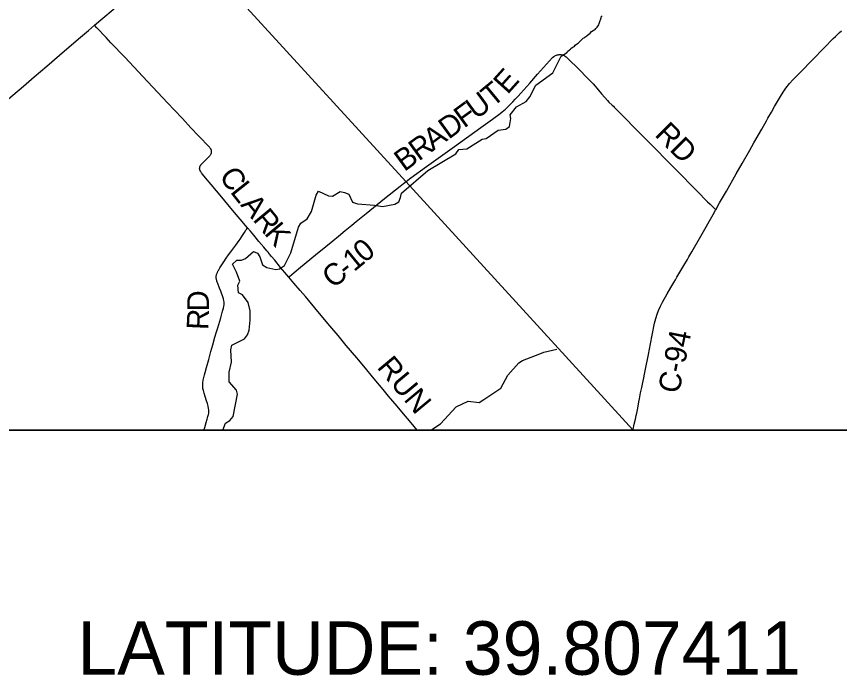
# Model space of a CAD drawing. Extents: x -1.4 to 35.4, y 0 to 22.
# Drawn here: x 19.08 to 21.235, y 12.413 to 14.137 of the extents above; entities that cross this region are included whole.
import ezdxf

# ---------------------------------------------------------------- set-up
doc = ezdxf.new("R2010")
doc.units = 0
for name, color, linetype in [('GM_X_County_Road', 7, 'Continuous'), ('GM_X_County_Road_Text', 7, 'Continuous'), ('GM_X_Minor_River', 7, 'Continuous'), ('GM_X_Township_Road', 7, 'Continuous'), ('GM_X_Township_Road_Text', 7, 'Continuous'), ('SC_Scratch1', 7, 'Continuous'), ('SH_Border', 7, 'Continuous'), ('SH_Text', 7, 'Continuous')]:
    doc.layers.add(name, color=color, linetype=linetype)

msp = doc.modelspace()

# ---------------------------------------------------------------- linework, layer by layer
at = {"layer": 'GM_X_County_Road'}
msp.add_line((20.6943, 13.0546), (20.6944, 13.0551), dxfattribs=at)
for points in [[(19.285, 14.1142), (19.3064, 14.1326), (19.3333, 14.1559), (19.3644, 14.1828), (19.38, 14.1961), (19.3968, 14.2106)], [(19.0431, 13.9076), (19.0988, 13.9553), (19.1264, 13.979), (19.1596, 14.0074), (19.193, 14.0362), (19.2247, 14.0631), (19.2479, 14.0829), (19.2693, 14.1008), (19.285, 14.1142)], [(20.9107, 13.6315), (20.9208, 13.6495), (20.9385, 13.6802), (20.9644, 13.7255), (20.98, 13.7527), (20.9996, 13.787), (21.0107, 13.8064), (21.0313, 13.8422), (21.0439, 13.8639), (21.0474, 13.8711), (21.0565, 13.8868), (21.0648, 13.9013), (21.0803, 13.9282), (21.0871, 13.9393), (21.0946, 13.95), (21.1038, 13.9616), (21.1133, 13.9722), (21.1323, 13.9918), (21.1642, 14.024), (21.1947, 14.0551), (21.2185, 14.0794), (21.2241, 14.0851), (21.2347, 14.0956), (21.2398, 14.1)], [(20.1001, 13.7052), (20.1125, 13.7148), (20.1538, 13.7446), (20.2273, 13.7972), (20.2957, 13.8464), (20.3264, 13.8682), (20.3466, 13.8837), (20.3518, 13.8881), (20.36, 13.8947), (20.3633, 13.8976), (20.3692, 13.9032), (20.38, 13.9143), (20.386, 13.9206), (20.3932, 13.9284), (20.4007, 13.9367), (20.424, 13.963), (20.4445, 13.9861), (20.4757, 14.0213), (20.4833, 14.0295), (20.4868, 14.0327), (20.4884, 14.0337), (20.4898, 14.0345), (20.4917, 14.0354), (20.4937, 14.0362), (20.4959, 14.0368), (20.4984, 14.0373), (20.5002, 14.0375), (20.5022, 14.0376), (20.5043, 14.0376), (20.5061, 14.0375), (20.5078, 14.0372), (20.5093, 14.0369), (20.5108, 14.0364), (20.5122, 14.0359), (20.5136, 14.0352), (20.5148, 14.0346), (20.517, 14.0331), (20.5188, 14.0318), (20.5206, 14.0303), (20.5334, 14.0181), (20.5435, 14.0081), (20.5835, 13.9675), (20.5896, 13.9609), (20.5948, 13.9548), (20.5992, 13.9496), (20.6121, 13.9345), (20.6203, 13.9251), (20.6274, 13.9175), (20.6312, 13.9134), (20.6397, 13.9052), (20.6428, 13.9022), (20.645, 13.9001), (20.6511, 13.894), (20.6554, 13.8895), (20.6606, 13.8842), (20.6657, 13.8789), (20.671, 13.8737), (20.6752, 13.8692), (20.6964, 13.8474), (20.7191, 13.8246), (20.7526, 13.7907), (20.7823, 13.7608), (20.8116, 13.7313), (20.8569, 13.6854), (20.8674, 13.6747), (20.8834, 13.6584), (20.8895, 13.6523), (20.8957, 13.6462), (20.9015, 13.6406), (20.9107, 13.6315)], [(19.7929, 13.4552), (19.7953, 13.4572), (19.8076, 13.4674), (19.8242, 13.4812), (19.8631, 13.5134), (19.89, 13.5354), (19.9084, 13.5503), (19.9229, 13.5621), (19.9408, 13.577), (19.958, 13.5914), (19.9696, 13.6008), (19.9961, 13.6214), (20.0433, 13.6606), (20.0843, 13.6928), (20.0934, 13.7), (20.1001, 13.7052)], [(20.6944, 13.0551), (20.6946, 13.0564), (20.6976, 13.0703), (20.7005, 13.0837), (20.7024, 13.0928), (20.7038, 13.0995), (20.7055, 13.108), (20.7075, 13.1176), (20.7097, 13.1286), (20.7112, 13.1366), (20.712, 13.1415), (20.7141, 13.1524), (20.717, 13.1664), (20.7189, 13.1755), (20.7224, 13.1919), (20.7244, 13.2016), (20.7296, 13.2278), (20.7312, 13.2357), (20.7345, 13.2528), (20.7398, 13.2802), (20.7443, 13.3034), (20.7508, 13.3345), (20.7539, 13.3465), (20.7573, 13.3579), (20.7611, 13.3678), (20.7662, 13.3792), (20.7716, 13.3897), (20.7838, 13.4114), (20.7935, 13.428), (20.8011, 13.4409), (20.8052, 13.4478), (20.8093, 13.4548), (20.8276, 13.4858), (20.8366, 13.5014), (20.8403, 13.5079), (20.848, 13.5214), (20.872, 13.5625), (20.9043, 13.6194), (20.91, 13.6304), (20.9107, 13.6315)], [(19.5708, 13.0546), (19.573, 13.0617), (19.5771, 13.0746), (19.5798, 13.0835), (19.5817, 13.0906), (19.5829, 13.0954), (19.5836, 13.0996), (19.5839, 13.1038), (19.5837, 13.108), (19.5833, 13.1116), (19.582, 13.1175), (19.5801, 13.1247), (19.5782, 13.1312), (19.5745, 13.1431), (19.5716, 13.1519), (19.5697, 13.1585), (19.5686, 13.1635), (19.568, 13.1685), (19.5679, 13.1736), (19.5683, 13.1786), (19.5694, 13.1854), (19.5701, 13.189), (19.571, 13.1927), (19.5728, 13.1995), (19.5744, 13.206), (19.578, 13.2191), (19.5838, 13.2394), (19.5866, 13.2503), (19.5895, 13.2604), (19.5946, 13.2784), (19.6, 13.2977), (19.6043, 13.3121), (19.6071, 13.3223), (19.6149, 13.3487), (19.6177, 13.3588), (19.6199, 13.366), (19.6223, 13.3743), (19.6233, 13.379), (19.6239, 13.3828), (19.6242, 13.3857), (19.6242, 13.3897), (19.6235, 13.3934), (19.6224, 13.398), (19.6209, 13.4032), (19.6169, 13.4133), (19.615, 13.4184), (19.6117, 13.4264), (19.6071, 13.4382), (19.6063, 13.4404), (19.6056, 13.4424), (19.605, 13.4444), (19.6044, 13.4463), (19.6039, 13.4485), (19.6036, 13.4502), (19.6033, 13.4518), (19.6031, 13.4535), (19.6031, 13.4551), (19.6032, 13.4568), (19.6034, 13.4583), (19.6037, 13.4599), (19.6042, 13.4617), (19.6048, 13.4635), (19.6056, 13.4655), (19.6065, 13.4676), (19.6077, 13.4704), (19.609, 13.4727), (19.6131, 13.4797), (19.6231, 13.4955), (19.6296, 13.5052), (19.6357, 13.5138), (19.6412, 13.5213), (19.6468, 13.5287), (19.6546, 13.5392), (19.6632, 13.5513), (19.6657, 13.5549), (19.6719, 13.5641), (19.6769, 13.5718), (19.6811, 13.578), (19.6821, 13.5795), (19.6853, 13.584)]]:
    msp.add_lwpolyline(points, dxfattribs=at)
at = {"layer": 'GM_X_Minor_River'}
for points in [[(20.5061, 14.0333), (20.5203, 14.0424), (20.5214, 14.0428), (20.523, 14.0458), (20.5276, 14.0499), (20.5303, 14.0517), (20.5318, 14.0536), (20.5352, 14.0562), (20.5383, 14.0581), (20.5406, 14.0592), (20.5429, 14.0622), (20.5464, 14.0652), (20.5502, 14.0678), (20.5525, 14.0689), (20.5537, 14.0712), (20.556, 14.073), (20.5579, 14.0745), (20.5613, 14.0775), (20.5636, 14.0801), (20.5659, 14.0813), (20.5682, 14.0831), (20.5705, 14.085), (20.5732, 14.0868), (20.5751, 14.0887), (20.5786, 14.0909), (20.582, 14.0932), (20.5851, 14.0977), (20.5897, 14.1007), (20.5928, 14.1025), (20.5947, 14.1036), (20.5966, 14.1059), (20.5985, 14.1078), (20.6005, 14.1096), (20.6043, 14.1153), (20.6059, 14.1187), (20.6067, 14.1213), (20.6075, 14.124), (20.6086, 14.1266), (20.6094, 14.1289), (20.6106, 14.1334), (20.6107, 14.1365), (20.613, 14.1387)], [(19.8413, 13.6078), (19.8526, 13.6272), (19.8652, 13.6701), (19.8711, 13.6799), (19.897, 13.668), (19.9075, 13.667), (19.9275, 13.6791), (19.9388, 13.6766), (19.9504, 13.6725), (19.9598, 13.6511), (19.973, 13.6467), (20.0172, 13.6439), (20.0383, 13.6396), (20.071, 13.6458), (20.081, 13.652), (20.0857, 13.6633), (20.0878, 13.6746), (20.1571, 13.7346), (20.2307, 13.7782), (20.2384, 13.7894), (20.2589, 13.7905), (20.2991, 13.8166), (20.3094, 13.8183), (20.3412, 13.8396), (20.3613, 13.8426), (20.3709, 13.8496), (20.374, 13.87), (20.373, 13.8795), (20.3894, 13.9004), (20.4142, 13.9151), (20.4239, 13.9266), (20.4401, 13.9577), (20.4846, 13.9898), (20.5061, 14.0333)], [(19.6206, 13.0546), (19.6279, 13.0727), (19.6391, 13.0797), (19.648, 13.0901), (19.6587, 13.1491), (19.6559, 13.1591), (19.6373, 13.1815), (19.6371, 13.2065), (19.6429, 13.2326), (19.6417, 13.2653), (19.6445, 13.277), (19.6775, 13.2934), (19.6853, 13.3042), (19.6897, 13.3163), (19.6922, 13.3428), (19.6919, 13.3667), (19.6866, 13.3889), (19.6722, 13.4089), (19.6613, 13.4144), (19.6598, 13.4342), (19.6646, 13.4447), (19.656, 13.4681), (19.6458, 13.4892), (19.657, 13.4996), (19.6695, 13.4993), (19.6795, 13.5037), (19.7011, 13.5222), (19.7112, 13.5182), (19.7175, 13.5086), (19.7243, 13.4875), (19.7355, 13.4805), (19.7594, 13.4754), (19.7689, 13.4768), (19.7823, 13.4852), (19.7982, 13.5187), (19.8185, 13.5858), (19.8248, 13.5963), (19.8413, 13.6078)], [(20.1654, 13.0546), (20.1901, 13.0714), (20.2316, 13.1154), (20.2626, 13.1303), (20.2914, 13.127), (20.3034, 13.1351), (20.348, 13.165), (20.3669, 13.1984), (20.3956, 13.2308), (20.4052, 13.2374), (20.45, 13.2544), (20.4607, 13.2591), (20.4946, 13.2663)]]:
    msp.add_lwpolyline(points, dxfattribs=at)
at = {"layer": 'GM_X_Township_Road'}
for points in [[(19.6853, 13.584), (19.6801, 13.5901), (19.6659, 13.6069), (19.6461, 13.6308), (19.6182, 13.6647), (19.5904, 13.6973), (19.5751, 13.7153), (19.5673, 13.7248), (19.5645, 13.7284), (19.5635, 13.7299), (19.5625, 13.7315), (19.5619, 13.7326), (19.5614, 13.7334), (19.561, 13.7345), (19.5606, 13.7354), (19.5603, 13.7364), (19.5601, 13.7374), (19.56, 13.7384), (19.5598, 13.7396), (19.5598, 13.7406), (19.5599, 13.7417), (19.5601, 13.7426), (19.5603, 13.7436), (19.5605, 13.7444), (19.561, 13.7454), (19.5614, 13.7464), (19.562, 13.7474), (19.5626, 13.7483), (19.5633, 13.7493), (19.5643, 13.7505), (19.5658, 13.752), (19.5674, 13.7537), (19.5713, 13.7576), (19.5788, 13.7649), (19.5836, 13.7696), (19.5864, 13.7729), (19.5876, 13.7743), (19.5886, 13.7756), (19.5893, 13.7767), (19.5899, 13.7778), (19.5903, 13.7787), (19.5907, 13.7798), (19.591, 13.7807), (19.5912, 13.7818), (19.5912, 13.7829), (19.5912, 13.7841), (19.5912, 13.7852), (19.591, 13.7862), (19.5907, 13.7872), (19.5904, 13.7881), (19.59, 13.789), (19.5895, 13.7899), (19.5889, 13.7908), (19.5882, 13.7916), (19.5867, 13.7934), (19.5853, 13.795), (19.5567, 13.8251), (19.5372, 13.8459), (19.5146, 13.8699), (19.4928, 13.8929), (19.4762, 13.9106), (19.4495, 13.9392), (19.4107, 13.9803), (19.3637, 14.0306), (19.3277, 14.0686), (19.315, 14.0822), (19.2908, 14.108), (19.285, 14.1142)], [(19.7417, 13.5167), (19.7389, 13.5201), (19.7353, 13.5244), (19.7275, 13.5333), (19.7149, 13.5485), (19.7013, 13.565), (19.6927, 13.5754), (19.6853, 13.584)], [(19.7929, 13.4552), (19.7877, 13.4612), (19.7718, 13.4805), (19.7562, 13.4993), (19.7481, 13.5091), (19.7431, 13.5151), (19.7417, 13.5167)], [(20.1293, 13.0546), (20.1216, 13.064), (20.1087, 13.0795), (20.0937, 13.0977), (20.0769, 13.1178), (20.0545, 13.1439), (20.0402, 13.1609), (20.0169, 13.189), (19.9893, 13.2218), (19.9709, 13.2436), (19.9435, 13.2766), (19.922, 13.3024), (19.9004, 13.3279), (19.8781, 13.3546), (19.8613, 13.3745), (19.8365, 13.4041), (19.8232, 13.4198), (19.8063, 13.4398), (19.7929, 13.4552)]]:
    msp.add_lwpolyline(points, dxfattribs=at)
at = {"layer": 'SC_Scratch1'}
msp.add_line((-1.4282, 13.0546), (35.3749, 13.0546), dxfattribs=at)
for points in [[(17.0598, 13.0546), (20.6952, 13.0546), (20.6941, 13.0557), (20.0998, 13.7058), (19.5313, 14.3263), (19.3146, 14.5543), (19.6799, 14.855), (19.0057, 14.9053)], [(22.1854, 14.6488), (20.9965, 14.7655), (20.2192, 14.8232), (19.6799, 14.855), (19.3146, 14.5543), (19.5313, 14.3263), (20.0998, 13.7058), (20.6941, 13.0557), (20.6952, 13.0546), (23.8598, 13.0546)]]:
    msp.add_lwpolyline(points, dxfattribs=at)
at = {"layer": 'SH_Border'}
msp.add_lwpolyline([(17.0598, 19.8546), (23.8598, 19.8546), (23.8598, 13.0546), (17.0598, 13.0546)], close=True, dxfattribs=at)

# ---------------------------------------------------------------- texts
at = {"layer": 'GM_X_County_Road_Text'}
for s, height, rotation, p in [('E', 0.0568, 47.9545, (20.3656, 13.9313)), ('T', 0.0568, 39.526, (20.3262, 13.898)), ('U', 0.0568, 36.1578, (20.283, 13.8662)), ('F', 0.0568, 36.0602, (20.2519, 13.8436)), ('D', 0.0568, 36.0619, (20.2115, 13.8142)), ('RD', 0.05682, 314.996, (20.7488, 13.8264)), ('A', 0.0568, 36.0617, (20.1711, 13.7847)), ('R', 0.0568, 36.0595, (20.1333, 13.7573)), ('B', 0.0568, 36.0604, (20.0956, 13.7298)), ('0', 0.0568, 40.0805, (19.9914, 13.4904)), ('1', 0.0568, 39.3292, (19.9637, 13.4677)), ('C', 0.0568, 39.1529, (19.9093, 13.4234)), ('-', 0.0568, 39.1954, (19.9455, 13.4529)), ('D', 0.0568, 90.4466, (19.5843, 13.3659)), ('R', 0.0568, 87.5404, (19.5823, 13.3162)), ('C-94', 0.05682, 78.6898, (20.8146, 13.1484))]:
    msp.add_text(s, height=height, rotation=rotation, dxfattribs=at).set_placement(p)
at = {"layer": 'GM_X_Township_Road_Text'}
for s, height, rotation, p in [('C', 0.0568, 304.7618, (19.6091, 13.7196)), ('L', 0.0568, 308.3506, (19.638, 13.6782)), ('A', 0.0568, 309.583, (19.6652, 13.6438)), ('R', 0.0568, 309.6138, (19.6971, 13.6052)), ('K', 0.0568, 309.8702, (19.727, 13.5691)), ('RUN', 0.05682, 309.7666, (20.0219, 13.2189))]:
    msp.add_text(s, height=height, rotation=rotation, dxfattribs=at).set_placement(p)
at = {"layer": 'SH_Text'}
msp.add_text('LATITUDE: 39.807411', height=0.14, dxfattribs=at).set_placement((19.2398, 12.4146))

doc.saveas('drawing.dxf')
